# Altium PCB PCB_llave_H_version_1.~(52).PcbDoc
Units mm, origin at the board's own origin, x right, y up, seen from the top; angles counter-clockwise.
Board outline 85.85 x 71.63 mm, 2 copper layers (Top Layer, Bottom Layer); 58 components, 33 nets, 168 pads, 1 vias.
Unrouted connection lines stored in the file: 18.
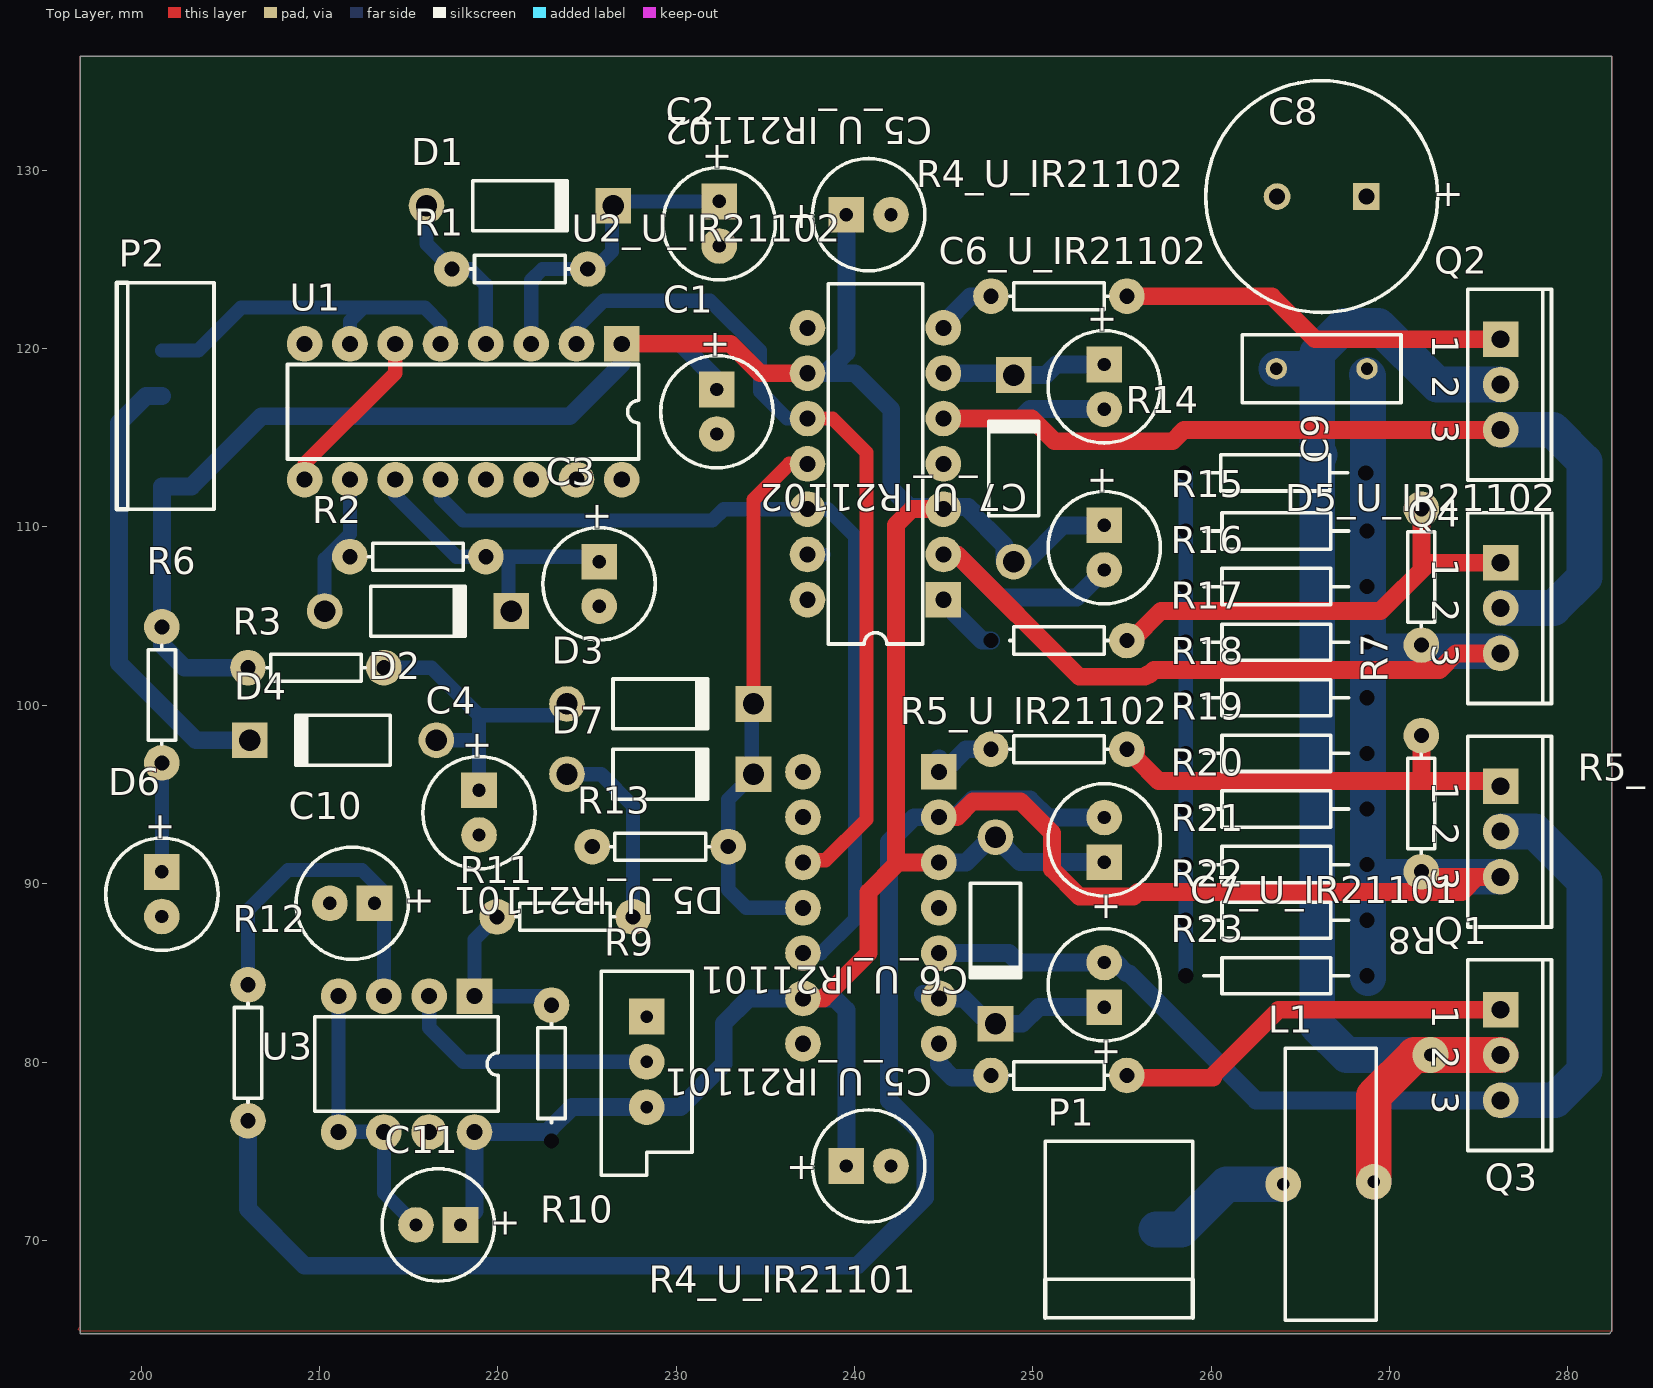
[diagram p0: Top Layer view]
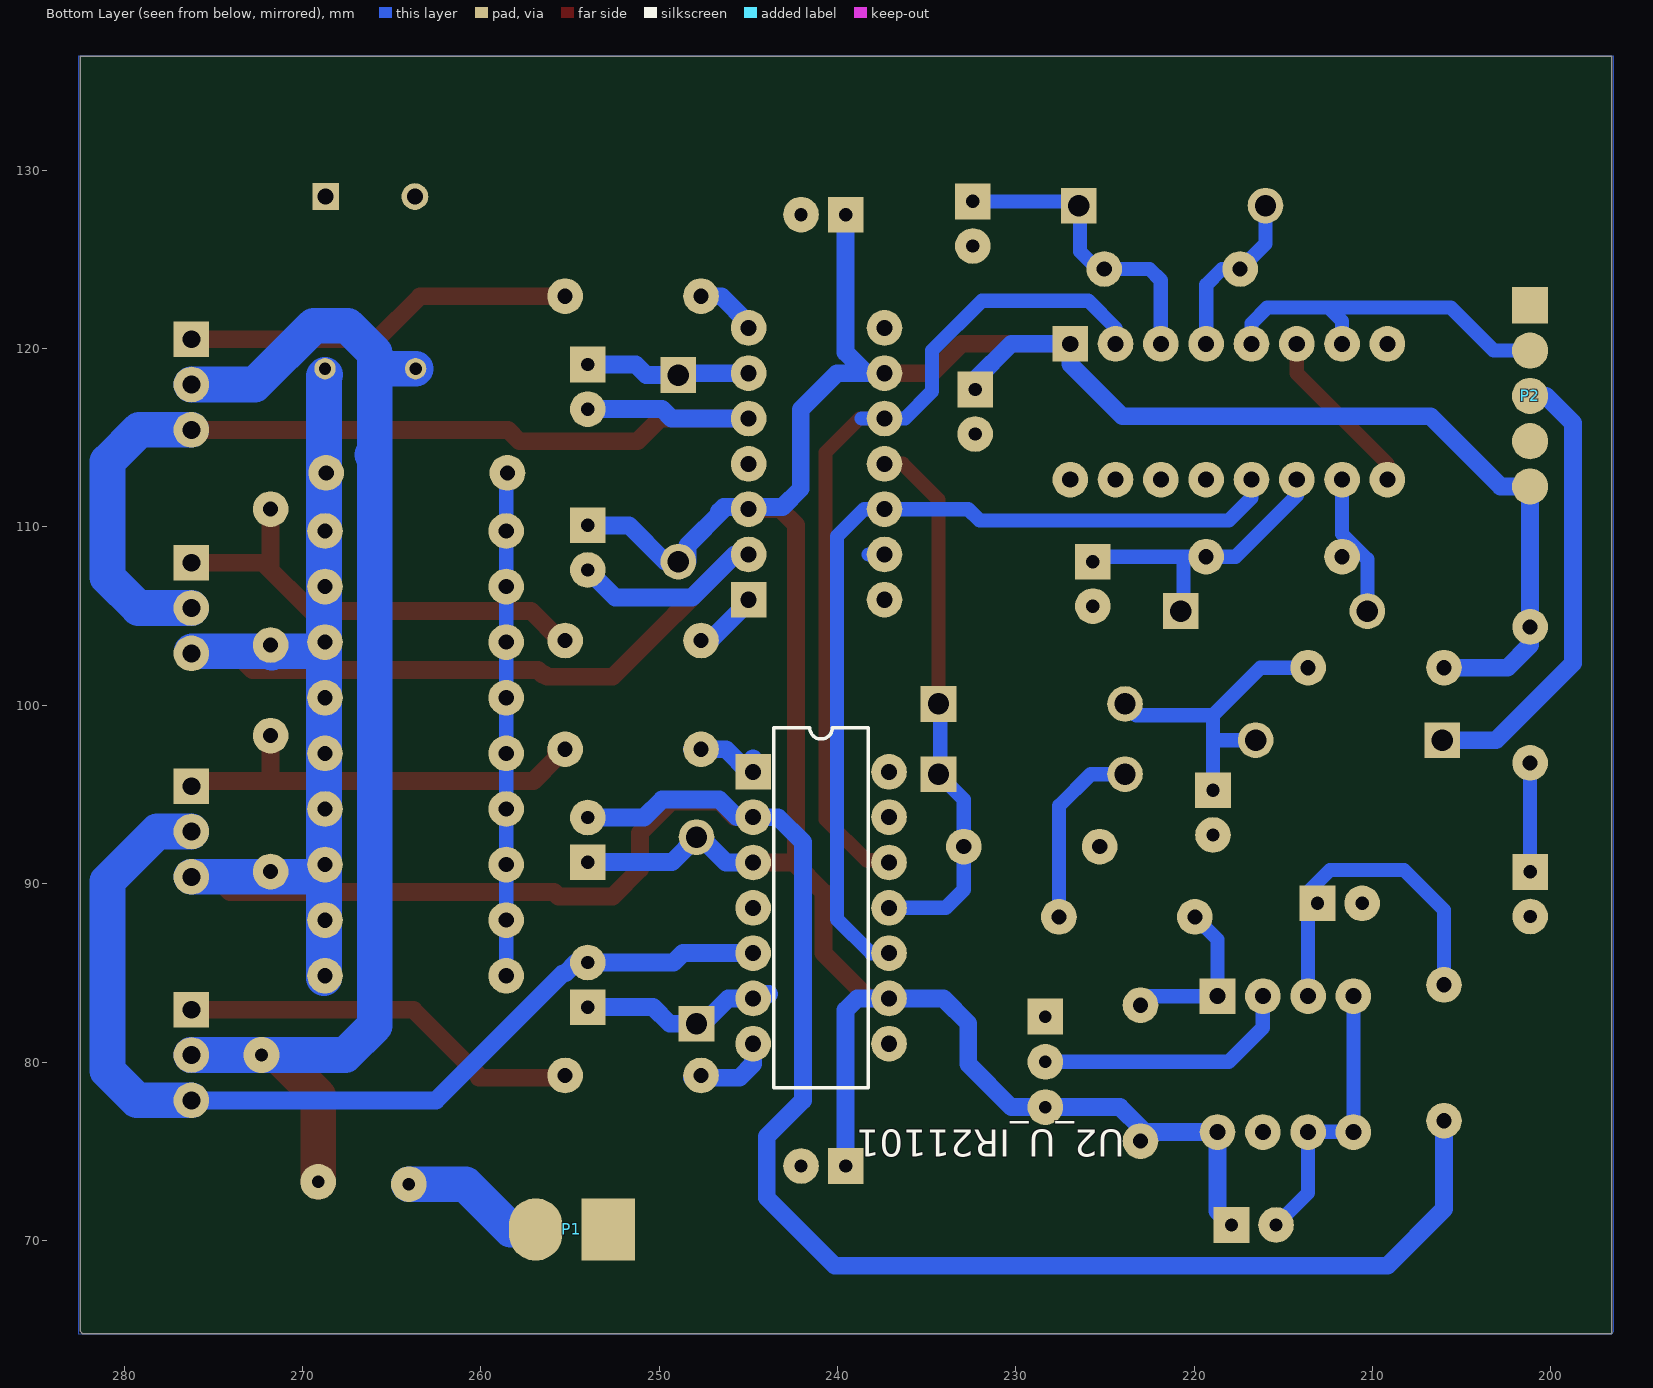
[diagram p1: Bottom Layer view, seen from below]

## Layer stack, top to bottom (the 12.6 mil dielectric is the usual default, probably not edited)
Top Layer: signal copper 0.0356
Dielectric: dielectric 0.32, FR-4, Dk 4.8
Bottom Layer: signal copper 0.0356

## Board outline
196.596,136.398 282.448,136.398 282.448,64.897 282.321,64.77 196.596,64.77

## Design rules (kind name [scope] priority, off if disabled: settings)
Clearance [All] p1: gap=0.4
ComponentClearance [All] p1: gap=0.254 collisioncheckmode=2 verticalgap=0.254
PolygonConnect [All] p1: connectstyle=Relief reliefconductorwidth=0.254 reliefentries=4 polygonreliefangle="90 Angle"
RoomDefinition U_IR21102 [InComponentClass('U_IR21102')] p1: confinementstyle=ConfineIn formatcopy=TRUE lockcomponents=FALSE outline 226.949,131.445 260.858,131.445 260.858,95.504 226.949,95.504
RoomDefinition U_Puente_H [InComponentClass('U_Puente_H')] p2: confinementstyle=ConfineIn formatcopy=TRUE lockcomponents=FALSE outline 282.448,135.255 282.448,64.897 247.65,64.897 247.65,135.255
RoomDefinition U_INITShutdown [InComponentClass('U_INITShutdown')] p3: confinementstyle=ConfineIn formatcopy=TRUE lockcomponents=FALSE outline 198.501,106.045 198.501,90.297 236.347,90.297 236.347,106.045
RoomDefinition U_Shutdown [InComponentClass('U_Shutdown')] p4: confinementstyle=ConfineOut formatcopy=TRUE lockcomponents=FALSE outline 201.041,103.886 202.438,103.886 202.438,100.584 201.041,100.584
RoomDefinition Llave_H_esquema [InComponentClass('Llave_H_esquema')] p5: confinementstyle=ConfineIn formatcopy=TRUE lockcomponents=FALSE outline 196.596,64.897 282.448,64.897 282.448,136.398 196.596,136.398
RoomDefinition U_4049 [InComponentClass('U_4049')] p6: confinementstyle=ConfineIn formatcopy=TRUE lockcomponents=FALSE outline 206.375,101.473 240.411,101.473 240.411,131.953 206.375,131.953
RoomDefinition U_IR21101 [InComponentClass('U_IR21101')] p7: confinementstyle=ConfineIn formatcopy=TRUE lockcomponents=FALSE outline 227.203,107.188 260.604,107.188 260.604,70.612 227.203,70.612
RoutingVias [All] p1: holewidth=0.711 width=1.27 viastyle="Through Hole" minholewidth=0.711 minwidth=1.27 maxholewidth=0.711 maxwidth=1.27
SolderMaskExpansion [All] p1: expansion=0.102
TestPointUsage [All] p1: valid=0 allowmultiple=FALSE
Testpoint [All] p1: side=15 testpointundercomponent=TRUE minsize=1.016 maxsize=2.54 preferedsize=1.524 minholesize=0 maxholesize=1.016 preferedholesize=0.813 testpointgrid=0.025 style=1023 order=0-112345678
Width [All] p1: maxlimit=3 minlimit=0.8 preferedwidth=1
18 further rules are at their usual default settings.

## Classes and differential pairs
component class U_INITShutdown: C4 D3 D4 R3
channel class IR2110: U_IR21101 U_IR21102
component class U_Shutdown: C10 C11 D7 R9 R10 R11 R12 R13 R14 R15 R16 R17 R18 R19 R20 R21 R22 R23 U3
component class U_Puente_H: C8 C9 L1 Q1 Q2 Q3 Q4 R7 R8
component class U_IR21102: C5_U_IR21102 C6_U_IR21102 C7_U_IR21102 D5_U_IR21102 R4_U_IR21102 R5_U_IR21102 U2_U_IR21102
component class U_IR21101: C5_U_IR21101 C6_U_IR21101 C7_U_IR21101 D5_U_IR21101 R4_U_IR21101 R5_U_IR21101 U2_U_IR21101
component class U_4049: C1 C2 C3 D1 D2 R1 R2 U1
component class Llave_H_esquema: D6 P1 P2 R6

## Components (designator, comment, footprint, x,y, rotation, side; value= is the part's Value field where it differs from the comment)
C1 "Cap Pol1" CAPPR2.5-6.3X5 232.283,116.459 r270 top
C2 "Cap Pol1" CAPPR2.5-6.3X5 232.41,127 r270 top
C3 "Cap Pol1" CAPPR2.5-6.3X5 225.679,106.807 r270 top
C4 "Cap Pol1" CAPPR2.5-6.3X5 218.948,93.98 r270 top
C5_U_IR21101 "Cap Pol1" CAPPR2.5-6.3X5 240.792,74.168 r0 top (schematic designator C5)
C5_U_IR21102 "Cap Pol1" CAPPR2.5-6.3X5 240.792,127.508 r0 top (schematic designator C5)
C6_U_IR21101 "Cap Pol1" CAPPR2.5-6.3X5 254,84.328 r90 top (schematic designator C6)
C6_U_IR21102 "Cap Pol1" CAPPR2.5-6.3X5 254,117.856 r270 top (schematic designator C6)
C7_U_IR21101 "Cap Pol1" CAPPR2.5-6.3X5 254,92.456 r90 top (schematic designator C7)
C7_U_IR21102 "Cap Pol1" CAPPR2.5-6.3X5 254,108.839 r270 top (schematic designator C7)
C8 "Cap Pol1" CAPPR5-13X16 266.192,128.524 r180 top
C9 "Cap" RAD-0.2 266.192,118.872 r180 top
C10 "Cap Pol1" CAPPR2.5-6.3X5 211.836,88.9 r180 top
C11 "Cap Pol1" CAPPR2.5-6.3X5 216.662,70.866 r180 top
D1 "Diode" DO-204AL 221.234,128.016 r0 top
D2 "Diode" DO-204AL 215.519,105.283 r0 top
D3 "Diode" DO-204AL 229.108,100.076 r0 top
D4 "Diode" DO-204AL 211.328,98.044 r180 top
D5_U_IR21101 "Diode" DO-204AL 247.904,87.376 r270 top (schematic designator D5)
D5_U_IR21102 "Diode" DO-204AL 248.92,113.284 r90 top (schematic designator D5)
D6 "LED0" CAPPR2.5-6.3X5 201.168,89.408 r270 top
D7 "Diode" DO-204AL 229.108,96.139 r0 top
L1 "Inductor" bobina_Choque 264.16,75.692 r270 top
P1 "Header 2" pwheader1x2 255.016,70.612 r0 top
P2 "MHDR1X5" HDR1X5 193.548,114.808 r270 top
Q1 "IRF3205" TO-220AB 276.225,80.391 r270 top
Q2 "IRF3205" TO-220AB 276.225,117.983 r270 top
Q3 "IRF3205" TO-220AB 276.225,92.922 r270 top
Q4 "IRF3205" TO-220AB 276.225,105.452 r270 top
R1 "Res2" AXIAL-0.3#1 221.234,124.46 r180 top
R2 "Res2" AXIAL-0.3#1 215.519,108.331 r0 top
R3 "Res2" AXIAL-0.3#1 209.804,102.108 r180 top
R4_U_IR21101 "Res2" AXIAL-0.3#1 251.46,79.248 r0 top (schematic designator R4)
R4_U_IR21102 "Res2" AXIAL-0.3#1 251.46,122.936 r0 top (schematic designator R4)
R5_U_IR21101 "Res2" AXIAL-0.3#1 251.46,97.536 r0 top (schematic designator R5)
R5_U_IR21102 "Res2" AXIAL-0.3#2 251.46,103.632 r0 top (schematic designator R5)
R6 "Res2" AXIAL-0.3#1 201.168,100.584 r90 top
R7 "Res2" AXIAL-0.3#1 271.78,107.188 r90 top
R8 "Res2" AXIAL-0.3#3 271.78,94.488 r90 top
R9 "RPot" VR5 228.346,80.01 r270 top
R10 "Res2" AXIAL-0.3#4 223.012,79.375 r270 top
R11 "Res2" AXIAL-0.3#1 223.774,88.138 r0 top
R12 "Res2" AXIAL-0.3#1 205.994,80.518 r90 top
R13 "Res2" AXIAL-0.3#1 229.108,92.075 r0 top
R14 "Res2" AXIAL-0.4#1 263.585,113.03 r0 top
R15 "Res2" AXIAL-0.4#1 263.652,109.774 r0 top
R16 "Res2" AXIAL-0.4#1 263.652,106.657 r0 top
R17 "Res2" AXIAL-0.4#1 263.652,103.539 r0 top
R18 "Res2" AXIAL-0.4#1 263.652,100.422 r0 top
R19 "Res2" AXIAL-0.4#1 263.652,97.305 r0 top
R20 "Res2" AXIAL-0.4#2 263.652,94.188 r0 top
R21 "Res2" AXIAL-0.4#2 263.652,91.07 r0 top
R22 "Res2" AXIAL-0.4#2 263.652,87.953 r0 top
R23 "Res2" AXIAL-0.4#2 263.652,84.836 r0 top
U1 "MC54HC4049J" 620-09 218.059,116.459 r180 top
U2_U_IR21101 "IR2110" PDIP14 240.919,88.646 r270 bottom (schematic designator U2)
U2_U_IR21102 "IR2110" PDIP14 241.173,113.538 r90 top (schematic designator U2)
U3 "LM393N" 626-05 214.884,79.883 r180 top

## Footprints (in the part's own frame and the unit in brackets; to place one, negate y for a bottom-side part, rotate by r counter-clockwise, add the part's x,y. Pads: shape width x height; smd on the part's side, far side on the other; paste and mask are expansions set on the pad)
620-09 [mm] "DIP; 16 Leads; Row Spacing 7.62 mm; Pitch 2.54 mm"
  rect 2x2 hole 0.9: 1(-8.89,-3.81)
  round 2 hole 0.9: 2(-6.35,-3.81) 3(-3.81,-3.81) 4(-1.27,-3.81) 5(1.27,-3.81) 6(3.81,-3.81) 7(6.35,-3.81) 8(8.89,-3.81) 9(8.89,3.81) 10(6.35,3.81) 11(3.81,3.81) 12(1.27,3.81) 13(-1.27,3.81) 14(-3.81,3.81) 15(-6.35,3.81) 16(-8.89,3.81)
  silkscreen extent -9.85,-2.65 9.85,2.65
626-05 [mm] "DIP; 8 Leads; Row Spacing 7.62 mm; Pitch 2.54 mm"
  rect 2x2 hole 0.9: 1(-3.81,-3.81)
  round 2 hole 0.9: 2(-1.27,-3.81) 3(1.27,-3.81) 4(3.81,-3.81) 5(3.81,3.81) 6(1.27,3.81) 7(-1.27,3.81) 8(-3.81,3.81)
  silkscreen extent -5.15,-2.65 5.15,2.65
AXIAL-0.3#1 [mm] "Resistor; 2 Leads"
  round 2 hole 0.85: 1(-3.81,0) 2(3.81,0)
  silkscreen extent -2.77,-0.76 2.77,0.76
AXIAL-0.3#2 [mm] "Resistor; 2 Leads"
  round 0 / inner round 0 / far side round 2 hole 0.85: 1(-3.81,0)
  round 2 hole 0.85: 2(3.81,0)
  silkscreen extent -2.77,-0.76 2.77,0.76
AXIAL-0.3#3 [mm] "Resistor; 2 Leads"
  round 2 hole 0.85 paste+0 mask+0.102: 1(-3.81,0)
  round 2 hole 0.85: 2(3.81,0)
  silkscreen extent -2.77,-0.76 2.77,0.76
AXIAL-0.3#4 [mm] "Resistor; 2 Leads"
  round 2 hole 0.85: 1(-3.81,0)
  round 0 / inner round 0 / far side round 2 hole 0.85: 2(3.81,0)
  silkscreen extent -2.77,-0.76 2.77,0.76
AXIAL-0.4#1 [mm] "Resistor; 2 Leads"
  round 0 / inner round 0 / far side round 2 hole 0.85: 1(-5.08,0) 2(5.08,0)
  silkscreen extent -4.06,-1.02 4.06,1.02
AXIAL-0.4#2 [mm] "Resistor; 2 Leads"
  round 0 / inner round 0 / far side round 2 hole 0.85: 1(-5.08,0)
  round 0 / inner round 0 / far side round 2 hole 0.85 unplated: 2(5.08,0)
  silkscreen extent -4.06,-1.02 4.06,1.02
bobina_Choque [mm]
  round 2 hole 0.7: 1(2.54,-0.127) 2(2.413,4.953)
  silkscreen extent -5.08,0 10.16,5.08
CAPPR2.5-6.3X5 [mm] "Capacitor, Electrolytic, Radial; Body 6.3 x 5 mm (Dia.xH typ); Pin Spacing 2.5 mm (typ)"
  rect 2x2 hole 0.75: 1(-1.25,0)
  round 2 hole 0.75: 2(1.25,0)
  silkscreen extent -3.15,-3.15 3.15,3.15
CAPPR5-13X16 [mm] "Capacitor, Electrolytic, Radial; Body 13 x 16 mm (Dia.xH typ); Pin Spacing 5 mm (typ)"
  rect 1.5x1.5 hole 0.9: 1(-2.5,0)
  round 1.5 hole 0.9: 2(2.5,0)
  silkscreen extent -6.5,-6.5 6.5,6.5
DO-204AL [mm] "Diode, Axial; Body 5.2 x 2.7 mm (LxDia. max), Lead Dia. 0.86 mm (max)"
  round 2 hole 1.2: 1(-5.23,0)
  rect 2x2 hole 1.2: 2(5.23,0)
  silkscreen extent -2.65,-1.4 2.75,1.4
HDR1X5 [mil]
  rect 80x80 smd far side: 1(-300,300)
  round 80 smd far side: 2(-200,300) 3(-100,300) 4(0,300) 5(100,300)
  silkscreen extent -350,200 150,415
PDIP14 [mm] "DIP; 14 Leads; Row Spacing 7.62 mm; Pitch 2.54 mm"
  rect 2x2 hole 0.9: 1(-7.62,-3.81)
  round 2 hole 0.9: 2(-5.08,-3.81) 3(-2.54,-3.81) 4(0,-3.81) 5(2.54,-3.81) 6(5.08,-3.81) 7(7.62,-3.81) 8(7.62,3.81) 9(5.08,3.81) 10(2.54,3.81) 11(0,3.81) 12(-2.54,3.81) 13(-5.08,3.81) 14(-7.62,3.81)
  silkscreen extent -10.1,-2.65 10.1,2.65
pwheader1x2 [mm]
  rect 3x3.5 smd far side: 1(-2.159,0)
  oval 3x3.5 smd far side: 2(1.905,0)
  silkscreen extent -4.32,-4.95 3.94,4.95
RAD-0.2 [mm] "Jumper Wire; 2 Leads"
  round 1.2 hole 0.7: 1(-2.54,0) 2(2.54,0)
  silkscreen extent -4.44,-1.91 4.44,1.91
TO-220AB [mm] "TO, Thru-Hole, Vertical, Heatsink Mounted; 3 In-Line Leads; Pitch 2.54 mm"
  rect 2x2 hole 1: 1(-2.54,0)
  round 2 hole 1: 2(0,0) 3(2.54,0)
  silkscreen extent -5.35,-1.85 5.35,2.85
VR5 [mm] "Potentiometer; 3 Leads"
  rect 2x2 hole 0.7: 1(-2.54,0)
  round 2 hole 0.7: 2(2.54,0) 3(0,0)
  silkscreen extent -5.08,-2.54 6.35,2.54

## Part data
C1 C2 C3 C4 C5_U_IR21101 C5_U_IR21102 C6_U_IR21101 C6_U_IR21102 C7_U_IR21101 C7_U_IR21102 C8 C10 C11: "Polarized Capacitor (Radial)"
C9: "Capacitor"
D1 D2 D3 D4 D5_U_IR21101 D5_U_IR21102 D7: "Default Diode"
D6: "Typical INFRARED GaAs LED"
P1: "Header, 2-Pin"
P2: "Header, 5-Pin"
Q1 Q2 Q3 Q4: "HEXFET Power MOSFET"
R1 R2 R3 R4_U_IR21101 R4_U_IR21102 R5_U_IR21101 R5_U_IR21102 R6 R7 R8 R10 R11 R12 R13 R14 R15 R16 R17 R18 R19 R20 R21 R22 R23: "Resistor"
R9: "Potentiometer"
U1: "Hex Inverting Buffer/Logic-Level Down Converter"
U2_U_IR21101 U2_U_IR21102: "High and Low Side Driver"
U3: "Dual Comparator"

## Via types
v1: diameter 2, hole 0.711, Top Layer to Bottom Layer, 1 vias

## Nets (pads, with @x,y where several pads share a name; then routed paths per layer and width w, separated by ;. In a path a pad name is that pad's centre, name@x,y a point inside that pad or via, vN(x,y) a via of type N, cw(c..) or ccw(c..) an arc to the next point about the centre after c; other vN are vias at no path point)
COM_U_IR21101: C7_U_IR21101.2 C7_U_IR21102.2 C9.1 Q3.3 Q4.3 R7.1 R8.1 R12.1 R14.2 R15.2 R16.2 R17.2 R18.2 R19.2 R20.2 R21.2 R22.2 R23.2 U2_U_IR21101.2 U2_U_IR21102.2 | length 217.5
  Top Layer w1: U2_U_IR21101.2 245.745,93.726 246.634,94.615 249.301,94.615 251.079,92.837 251.079,90.805 252.603,89.281 255.646,89.281 255.9,89.535 274.066,89.535 274.913,90.382 ; U2_U_IR21102.2 245.745,108.458 252.603,101.6 256.286,101.6 256.413,101.727 256.54,101.727 256.794,101.981 272.796,101.981 273.727,102.912 Q4.3 ; R8.1@271.78,90.382 Q3.3
  Bottom Layer w1: R12.1 205.994,71.755 209.169,68.58 240.157,68.58 243.967,72.39 243.967,75.819 241.935,77.851 241.935,92.329 243.332,93.726 245.633,93.726 246.629,94.722 249.829,94.722 250.845,93.706 C7_U_IR21101.2 ; U2_U_IR21102.2 245.745,108.458 248.158,106.045 252.456,106.045 C7_U_IR21102.2 ; R7.1@271.713,102.997 271.798,102.912 Q4.3
  Bottom Layer w2: C9.1@268.732,118.526 268.792,118.465 R23.2@268.792,84.709 ; R21.2@268.792,90.382 Q3.3 ; R17.2@268.792,103.031 Q4.3@276.191,103.031 ; R7.1@271.713,102.965 R7.1@271.78,103.031
GND: C1.2 C2.2 C3.2 C4.2 C5_U_IR21101.2 C5_U_IR21102.2 C8.2 C10.2 C11.2 D6.2 P1.1 P2.4 R9.1 R13.1 R14.1 R15.1 R16.1 R17.1 R18.1 R19.1 R20.1 R21.1 R22.1 R23.1 U1.8 U2_U_IR21101.13 U2_U_IR21102.13 U3.4 U3.5 U3.6 | length 45.2
  Top Layer w0.8: U3.5 211.094,76.093 U3.5@211.074,76.113 ; U3.6@213.594,76.093 U3.6
  Bottom Layer w0.8: U3.5 U3.4 ; U3.5@211.094,76.093 U3.6@213.594,76.093 ; U3.6 213.614,72.664 C11.2 ; U2_U_IR21102.13 U2_U_IR21102.13@238.252,108.458 ; R23.1 R14.1@258.572,112.963
HIN_U_IR21101: U1.12 U2_U_IR21101.10 U2_U_IR21102.12 | length 50.9
  Bottom Layer w0.8: U1.12 216.789,111.633 218.059,110.363 232.029,110.363 232.664,110.998 238.506,110.998 240.03,109.474 240.03,88.011 238.125,86.106 U2_U_IR21101.10
HIN_U_IR21102: U1.2 U2_U_IR21101.12 U2_U_IR21102.10 | length 48.9
  Top Layer w0.8: U2_U_IR21101.12@237.236,91.313 238.379,91.313 240.665,93.599 240.665,114.173 238.76,116.078 U2_U_IR21102.10
  Bottom Layer w0.8: U1.2 224.409,121.158 225.933,122.682 231.902,122.682 234.696,119.888 234.696,117.602 236.22,116.078 238.633,116.078
HO1: Q2.1 R4_U_IR21102.2 | length 22
  Top Layer w1: R4_U_IR21102.2 263.398,122.936 265.811,120.523 Q2.1
HO2: Q1.1 R4_U_IR21101.2 | length 22
  Top Layer w1: R4_U_IR21101.2@255.905,79.121 260.096,79.121 ; 259.969,79.121 263.779,82.931 Q1.1
IN_SD: D4.2 P2.3 | length 25.6
  Bottom Layer w1: P2.3 200.279,117.348 198.755,115.824 198.755,102.362 203.073,98.044 D4.2
LO1: Q4.1 R5_U_IR21102.2 R7.2 | length 26.4
  Top Layer w1: R5_U_IR21102.2 255.524,103.632 257.175,105.283 269.494,105.283 272.203,107.992 Q4.1 ; R7.2@271.78,111.252 271.78,107.592 271.791,107.58
LO2: Q3.1 R5_U_IR21101.2 R8.2 | length 24.5
  Top Layer w1: R5_U_IR21101.2@255.778,97.536 255.778,97.028 257.048,95.758 275.929,95.758 Q3.1 ; R8.2@271.526,98.679 R8.2@271.78,98.425 ; 271.78,95.758 R8.2
MOTOR+: C6_U_IR21102.2 Q2.3 Q4.2 U2_U_IR21102.5 | length 58.6
  Top Layer w1: U2_U_IR21102.5 249.936,116.078 251.206,114.808 257.836,114.808 258.471,115.443 Q2.3
  Bottom Layer w1: U2_U_IR21102.5 249.301,116.078 249.829,116.606 C6_U_IR21102.2
  Bottom Layer w2: Q4.2 279.188,105.452 280.924,107.188 280.924,113.665 279.146,115.443 Q2.3
MOTOR-: C6_U_IR21101.2 Q1.3 Q3.2 U2_U_IR21101.5 | length 56.8
  Bottom Layer w1: U2_U_IR21101.5 248.666,86.106 249.194,85.578 254.655,85.578 255.255,84.978 255.382,84.978 262.509,77.851 Q1.3
  Bottom Layer w2: Q1.3 279.273,77.851 280.924,79.502 280.924,90.128 278.13,92.922 Q3.2
NetC2_1: C2.1 D1.2 R1.1 U1.3 | length 17.4
  Bottom Layer w0.8: U1.3 221.869,123.825 222.504,124.46 225.425,124.46 226.403,125.438 226.403,127.955 226.698,128.25 C2.1
NetC3_1: C3.1 D2.2 R2.2 U1.11 | length 17
  Bottom Layer w0.8: U1.11 214.249,111.76 217.678,108.331 225.405,108.331 C3.1 ; 220.599,108.331 220.599,105.433 D2.2
NetC4_1: C4.1 D3.1 D4.1 R3.1 | length 18.2
  Bottom Layer w0.8: R3.1 216.281,102.108 218.948,99.441 ; D4.1 218.948,98.044 ; C4.1 218.948,99.441 ; D3.1 223.243,99.441 218.948,99.441
NetC6_U_IR21101_1: C6_U_IR21101.1 D5_U_IR21101.2 U2_U_IR21101.6 | length 10.8
  Bottom Layer w1: U2_U_IR21101.6@243.84,83.82 U2_U_IR21101.6@244.602,83.82 ; U2_U_IR21101.6 246.126,83.566 D5_U_IR21101.2@247.673,82.019 ; D5_U_IR21101.2 249.405,82.146 250.337,83.078 C6_U_IR21101.1
NetC6_U_IR21102_1: C6_U_IR21102.1 D5_U_IR21102.2 U2_U_IR21102.6 | length 9.8
  Bottom Layer w1: U2_U_IR21102.6 248.308,118.618 248.412,118.514 250.721,118.514 251.313,119.106 C6_U_IR21102.1 ; D5_U_IR21102.2@248.943,118.872 D5_U_IR21102.2@249.301,118.514
NetC10_1: C10.1 R12.2 U3.3 | length 19.1
  Bottom Layer w0.8: R12.2 205.994,88.519 208.24,90.765 212.384,90.765 213.614,89.535 U3.3
NetD1_1: D1.1 R1.2 U1.4 | length 9.7
  Bottom Layer w0.8: D1.1 216.004,125.88 R1.2 218.44,124.46 219.329,123.571 U1.4
NetD2_1: D2.1 R2.1 U1.10 | length 8
  Bottom Layer w0.8: D2.1 210.289,108.181 211.709,109.601 U1.10
NetD6_1: D6.1 R6.1 | length 6.1
  Bottom Layer w0.8: D6.1 R6.1
NetD7_1: D7.1 R11.2 | length 10.7
  Bottom Layer w0.8: D7.1 225.806,96.139 227.584,94.361 R11.2
NetR4_U_IR21101_1: R4_U_IR21101.1 U2_U_IR21101.7 | length 4.9
  Bottom Layer w1: U2_U_IR21101.7 244.729,79.883 245.491,79.121 R4_U_IR21101.1@248.158,79.121
NetR4_U_IR21102_1: R4_U_IR21102.1 U2_U_IR21102.7 | length 3.8
  Bottom Layer w1: U2_U_IR21102.7 244.983,121.412 246.507,122.936 R4_U_IR21102.1@247.904,122.936
NetR5_U_IR21101_1: R5_U_IR21101.1 U2_U_IR21101.1 | length 4.7
  Bottom Layer w1: U2_U_IR21101.1@244.729,97.028 U2_U_IR21101.1 244.983,96.266 246.253,97.536 R5_U_IR21101.1@248.158,97.536
NetR5_U_IR21102_1: R5_U_IR21102.1 U2_U_IR21102.1 | length 3.7
  Bottom Layer w1: U2_U_IR21102.1 244.983,105.791 247.142,103.632 R5_U_IR21102.1
NetR9_3: R9.3 U3.2 | length 14.8
  Bottom Layer w0.8: U3.2 216.154,81.915 218.059,80.01 R9.3
NetR10_1: R10.1 R11.1 U3.1 | length 9.5
  Bottom Layer w0.8: R11.1 218.694,86.868 U3.1 222.504,83.693 R10.1
NetU1_6: U1.6 U1.9 | length 9.9
  Top Layer w0.8: U1.9 209.169,113.538 214.249,118.618 U1.6
  Bottom Layer w0.8: U1.9 U1.9@209.169,112.776
PWM: P2.2 U1.5 U1.7 | length 20.5
  Bottom Layer w0.8: P2.2 203.2,119.888 205.613,122.301 215.9,122.301 216.789,121.412 U1.5 ; U1.7 211.709,121.539 212.471,122.301
SD: D3.2 D7.2 R13.2 U2_U_IR21101.11 U2_U_IR21102.11 | length 31.1
  Top Layer w0.8: D3.2 234.338,111.529 236.347,113.538 U2_U_IR21102.11
  Bottom Layer w0.8: D7.2@234.241,96.042 234.241,99.979 D3.2 ; D7.2 232.918,94.719 232.918,89.662 233.934,88.646 U2_U_IR21101.11
VCC_MOTOR: L1.1 P1.2 | length 8.2
  Bottom Layer w2: P1.2 258.318,70.612 260.858,73.152 L1.1
VCC_MOTOR_FILTRADO: C8.1 C9.2 L1.2 Q1.2 Q2.2 | length 76.4
  Top Layer w2: L1.2 269.113,78.105 271.399,80.391 Q1.2
  Bottom Layer w2: C9.2 265.811,118.872 265.938,118.745 ; 265.938,113.919 266.065,114.046 ; Q1.2 267.589,80.391 265.938,82.042 265.938,119.761 267.462,121.285 269.367,121.285 272.669,117.983 Q2.2
  other v1: 272.288,80.391
VDD: C1.1 C5_U_IR21101.1 C5_U_IR21102.1 C7_U_IR21101.1 C7_U_IR21102.1 C11.1 D5_U_IR21101.1 D5_U_IR21102.1 P2.5 R3.2 R6.2 R9.2 R10.2 U1.1 U2_U_IR21101.3 U2_U_IR21101.9 U2_U_IR21102.3 U2_U_IR21102.9 U3.8 | length 181.7
  Top Layer w0.8: C11.1 C11.1@217.912,71.481 ; U3.8@218.567,76.327 218.694,76.2 U3.8
  Top Layer w1: U1.1 233.045,120.269 234.696,118.618 U2_U_IR21102.9 ; U2_U_IR21101.9 238.252,83.566 240.792,86.106 240.792,89.535 242.443,91.186 U2_U_IR21101.3 ; 242.316,91.059 242.316,110.109 243.205,110.998 U2_U_IR21102.3
  Bottom Layer w0.8: R10.2@222.994,76.309 R10.2@223.012,76.292 ; C1.1 C1.1@232.283,118.11
  Bottom Layer w1: R3.2 202.438,102.108 201.168,103.378 P2.5 202.819,112.268 206.756,116.205 224.028,116.205 226.949,119.126 U1.1 230.251,120.269 232.283,118.237 C1.1 ; C11.1 218.694,71.648 U3.8 R10.2@222.758,76.073 ; R10.2@222.994,76.309 224.155,77.47 230.251,77.47 232.664,79.883 232.664,82.169 234.061,83.566 238.887,83.566 239.542,82.911 C5_U_IR21101.1 ; U2_U_IR21102.9 240.03,118.618 242.062,116.586 242.062,112.141 243.078,111.125 246.38,111.125 246.634,110.871 ; 238.379,118.618 239.542,119.781 C5_U_IR21102.1 ; U2_U_IR21101.3 246.253,91.186 D5_U_IR21101.1@247.546,92.479 ; 246.38,110.998 248.412,108.966 D5_U_IR21102.1@248.412,108.054 ; D5_U_IR21101.1 247.904,92.583 249.281,91.206 C7_U_IR21101.1 ; D5_U_IR21102.1 249.659,108.054 251.694,110.089 C7_U_IR21102.1
pads on no net: P2.1 U1.13 U1.14 U1.15 U1.16 U2_U_IR21101.4 U2_U_IR21101.8 U2_U_IR21101.14 U2_U_IR21102.4 U2_U_IR21102.8 U2_U_IR21102.14 U3.7

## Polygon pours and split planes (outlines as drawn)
GND on Bottom Layer (solid, remove dead copper, shelved): 196.469,136.398 282.575,136.398 282.575,64.77 196.596,64.77 196.469,64.897
GND on Top Layer (solid, remove dead copper, shelved): 196.596,136.398 282.448,136.398 282.448,64.897 196.596,64.897 196.469,65.024 196.596,65.151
